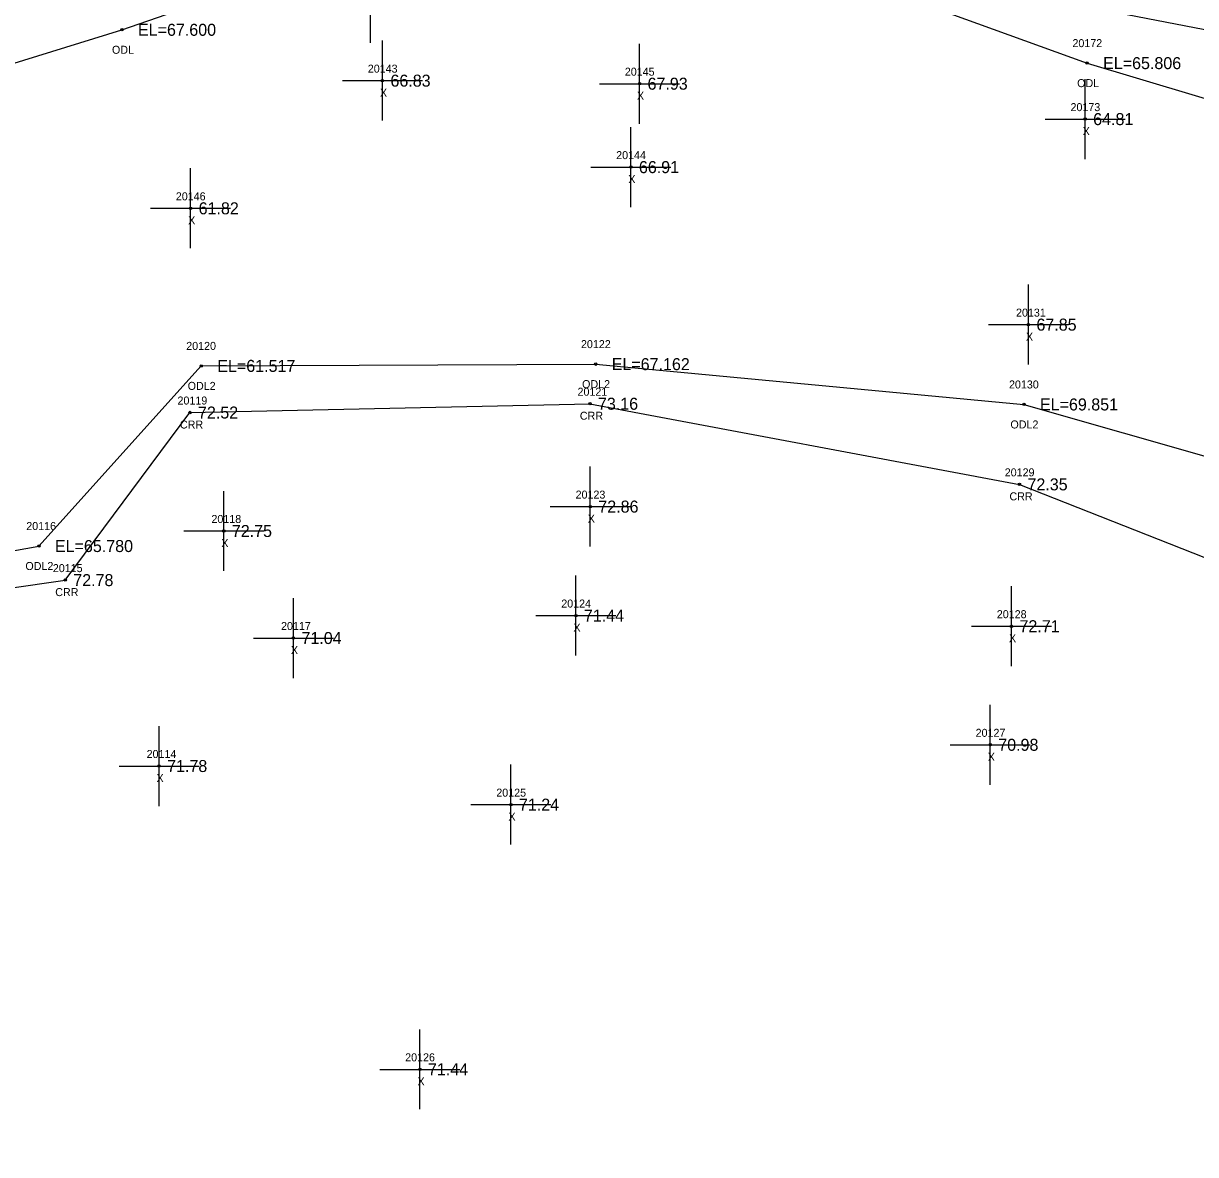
# Model space of a CAD drawing. Extents: x 2505300 to 2506184, y 912965 to 913825.
# Drawn here: x 2505870.9 to 2506017.4, y 913381.3 to 913522.7 of the extents above; entities that cross this region are included whole.
import ezdxf

# ---------------------------------------------------------------- set-up
doc = ezdxf.new("R2010")
doc.units = 0
for name, color, linetype in [('RD_EX_H2O', 7, 'Continuous'), ('RD_EX_H2O_txCode', 7, 'Continuous'), ('RD_EX_Misc', 7, 'Continuous'), ('RD_EX_Misc_txCode', 7, 'Continuous'), ('RD_EX_TX_H2O_ELEV', 7, 'Continuous'), ('RD_EX_TX_Misc_ELEV', 7, 'Continuous'), ('RD_SMD_Locator', 7, 'Continuous')]:
    doc.layers.add(name, color=color, linetype=linetype)

msp = doc.modelspace()

# ---------------------------------------------------------------- linework, layer by layer
at = {"layer": 'RD_EX_H2O'}
for points in [[(2505785.34, 913689.17), (2505760.31, 913663.21), (2505743.1, 913648.56), (2505723.59, 913620.14), (2505672.59, 913632.18), (2505661.09, 913622.14), (2505712.19, 913587.82), (2505787.26, 913549.76), (2505800.1, 913534.14), (2505825.87, 913510.39), (2505850.5, 913511.75), (2505883.26, 913521.88), (2505912.04, 913531.86), (2505948.81, 913534.96), (2505974.98, 913528.19), (2506003.87, 913517.71), (2506051.32, 913503.49), (2506114.3, 913484.75), (2506121.45, 913493.97), (2506156, 913550.08)], [(2505762.26, 913658.11), (2505746.15, 913644.25), (2505726.47, 913615.21), (2505674.21, 913628.01), (2505666.25, 913620.58), (2505714.6, 913592.15), (2505793.9, 913560.45), (2505801.32, 913552.8), (2505803.7, 913539.77), (2505832.63, 913516.96), (2505848.42, 913517.19), (2505881.86, 913528.44), (2505910.2, 913538.78), (2505939.3, 913544.45), (2505946.25, 913542.54), (2505974.65, 913535.18), (2506004.11, 913524.7), (2506052.03, 913515.47), (2506115.49, 913494.68), (2506138.05, 913548.89)], [(2505660.9, 913411.21), (2505684.62, 913438.72), (2505715.28, 913467.7), (2505742.46, 913486.6), (2505763.96, 913488.43), (2505794.61, 913469.83), (2505812.57, 913467.2), (2505833.64, 913450.28), (2505872.88, 913457.34), (2505893.17, 913479.86), (2505942.46, 913480.08), (2505995.98, 913475.04), (2506045.33, 913460.93), (2506077.87, 913439.29), (2506087.99, 913429.78), (2506108.19, 913381.27)], [(2505789.47, 913464.31), (2505795.69, 913463.1), (2505812.13, 913464.37), (2505832.03, 913446.73), (2505876.17, 913453.08), (2505891.76, 913474.03), (2505941.74, 913475.13), (2505995.42, 913465.05), (2506040.13, 913447.4), (2506076.3, 913432.47), (2506096.96, 913385.48)]]:
    msp.add_lwpolyline(points, dxfattribs=at)
at = {"layer": 'RD_EX_Misc'}
for p, q in [((2505914.32, 913520.24), (2505914.32, 913530.24)), ((2505915.81, 913510.52), (2505915.81, 913520.52)), ((2505947.94, 913510.14), (2505947.94, 913520.14)), ((2505910.81, 913515.52), (2505920.81, 913515.52)), ((2505942.94, 913515.14), (2505952.94, 913515.14)), ((2506003.63, 913505.71), (2506003.63, 913515.71)), ((2505998.63, 913510.71), (2506008.63, 913510.71)), ((2505946.86, 913499.71), (2505946.86, 913509.71)), ((2505891.84, 913494.56), (2505891.84, 913504.56)), ((2505941.86, 913504.71), (2505951.86, 913504.71)), ((2505886.84, 913499.56), (2505896.84, 913499.56)), ((2505996.54, 913480.02), (2505996.54, 913490.02)), ((2505991.54, 913485.02), (2506001.54, 913485.02)), ((2505941.79, 913457.27), (2505941.79, 913467.27)), ((2505895.99, 913454.22), (2505895.99, 913464.22)), ((2505936.79, 913462.27), (2505946.79, 913462.27)), ((2505890.99, 913459.22), (2505900.99, 913459.22)), ((2505939.99, 913443.65), (2505939.99, 913453.65)), ((2505994.42, 913442.32), (2505994.42, 913452.32)), ((2505904.69, 913440.84), (2505904.69, 913450.84)), ((2505934.99, 913448.65), (2505944.99, 913448.65)), ((2505989.42, 913447.32), (2505999.42, 913447.32)), ((2505899.69, 913445.84), (2505909.69, 913445.84)), ((2505991.77, 913427.49), (2505991.77, 913437.49)), ((2505887.9, 913424.84), (2505887.9, 913434.84)), ((2505986.77, 913432.49), (2505996.77, 913432.49)), ((2505882.9, 913429.84), (2505892.9, 913429.84)), ((2505931.87, 913420.01), (2505931.87, 913430.01)), ((2505926.87, 913425.01), (2505936.87, 913425.01)), ((2505920.5, 913386.92), (2505920.5, 913396.92)), ((2505915.5, 913391.92), (2505925.5, 913391.92))]:
    msp.add_line(p, q, dxfattribs=at)
at = {"layer": 'RD_SMD_Locator'}
for centre in [(2505883.26, 913521.88), (2506003.87, 913517.71), (2505915.81, 913515.52), (2505947.94, 913515.14), (2506003.63, 913510.71), (2505946.86, 913504.71), (2505891.84, 913499.56), (2505996.54, 913485.02), (2505893.17, 913479.86), (2505942.46, 913480.08), (2505941.74, 913475.13), (2505995.98, 913475.04), (2505891.76, 913474.03), (2505995.42, 913465.05), (2505941.79, 913462.27), (2505895.99, 913459.22), (2505872.88, 913457.34), (2505876.17, 913453.08), (2505939.99, 913448.65), (2505994.42, 913447.32), (2505904.69, 913445.84), (2505991.77, 913432.49), (2505887.9, 913429.84), (2505931.87, 913425.01), (2505920.5, 913391.92)]:
    msp.add_circle(centre, 0.15, dxfattribs=at)

# ---------------------------------------------------------------- texts
at = {"layer": 'RD_EX_H2O_txCode'}
for s, p in [('20172', (2506002.04, 913519.71)), ('ODL', (2505882.01, 913518.88)), ('ODL', (2506002.63, 913514.71)), ('20120', (2505891.29, 913481.86)), ('20122', (2505940.62, 913482.08)), ('ODL2', (2505891.47, 913476.86)), ('ODL2', (2505940.76, 913477.08)), ('20130', (2505994.11, 913477.04)), ('20121', (2505940.19, 913476.13)), ('20119', (2505890.2, 913475.03)), ('CRR', (2505940.48, 913473.13)), ('CRR', (2505890.5, 913472.03)), ('ODL2', (2505994.29, 913472.04)), ('20129', (2505993.58, 913466.05)), ('CRR', (2505994.17, 913463.05)), ('20116', (2505871.3, 913459.34)), ('ODL2', (2505871.19, 913454.34)), ('20115', (2505874.62, 913454.08)), ('CRR', (2505874.92, 913451.08))]:
    msp.add_text(s, height=1, dxfattribs=at).set_placement(p)
at = {"layer": 'RD_EX_Misc_txCode'}
for s, p in [('20143', (2505913.98, 913516.52)), ('20145', (2505946.1, 913516.14)), ('X', (2505915.5, 913513.52)), ('X', (2505947.62, 913513.14)), ('20173', (2506001.8, 913511.71)), ('X', (2506003.32, 913508.71)), ('20144', (2505945.02, 913505.71)), ('X', (2505946.54, 913502.71)), ('20146', (2505889.99, 913500.56)), ('X', (2505891.53, 913497.56)), ('20131', (2505994.99, 913486.02)), ('X', (2505996.23, 913483.02)), ('20123', (2505939.95, 913463.27)), ('20118', (2505894.44, 913460.22)), ('X', (2505941.47, 913460.27)), ('X', (2505895.67, 913457.22)), ('20124', (2505938.16, 913449.65)), ('20128', (2505992.59, 913448.32)), ('20117', (2505903.14, 913446.84)), ('X', (2505939.68, 913446.65)), ('X', (2505994.11, 913445.32)), ('X', (2505904.37, 913443.84)), ('20127', (2505989.94, 913433.49)), ('20114', (2505886.34, 913430.84)), ('X', (2505991.46, 913430.49)), ('X', (2505887.58, 913427.84)), ('20125', (2505930.04, 913426.01)), ('X', (2505931.56, 913423.01)), ('20126', (2505918.65, 913392.92)), ('X', (2505920.19, 913389.92))]:
    msp.add_text(s, height=1, dxfattribs=at).set_placement(p)
at = {"layer": 'RD_EX_TX_H2O_ELEV'}
for s, p in [('EL=67.600', (2505885.26, 913521.13)), ('EL=65.806', (2506005.87, 913516.96)), ('EL=67.162', (2505944.46, 913479.33)), ('EL=61.517', (2505895.17, 913479.11)), ('73.16', (2505942.74, 913474.38)), ('EL=69.851', (2505997.98, 913474.29)), ('72.52', (2505892.76, 913473.28)), ('72.35', (2505996.42, 913464.3)), ('EL=65.780', (2505874.88, 913456.59)), ('72.78', (2505877.17, 913452.33))]:
    msp.add_text(s, height=1.5, dxfattribs=at).set_placement(p)
at = {"layer": 'RD_EX_TX_Misc_ELEV'}
for s, p in [('66.83', (2505916.81, 913514.77)), ('67.93', (2505948.94, 913514.39)), ('64.81', (2506004.63, 913509.96)), ('66.91', (2505947.86, 913503.96)), ('61.82', (2505892.84, 913498.81)), ('67.85', (2505997.54, 913484.27)), ('72.86', (2505942.79, 913461.52)), ('72.75', (2505896.99, 913458.47)), ('71.44', (2505940.99, 913447.9)), ('72.71', (2505995.42, 913446.57)), ('71.04', (2505905.69, 913445.09)), ('70.98', (2505992.77, 913431.74)), ('71.78', (2505888.9, 913429.09)), ('71.24', (2505932.87, 913424.26)), ('71.44', (2505921.5, 913391.17))]:
    msp.add_text(s, height=1.5, dxfattribs=at).set_placement(p)

doc.saveas('drawing.dxf')
